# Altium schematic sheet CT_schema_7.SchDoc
size 278 x 170 mm
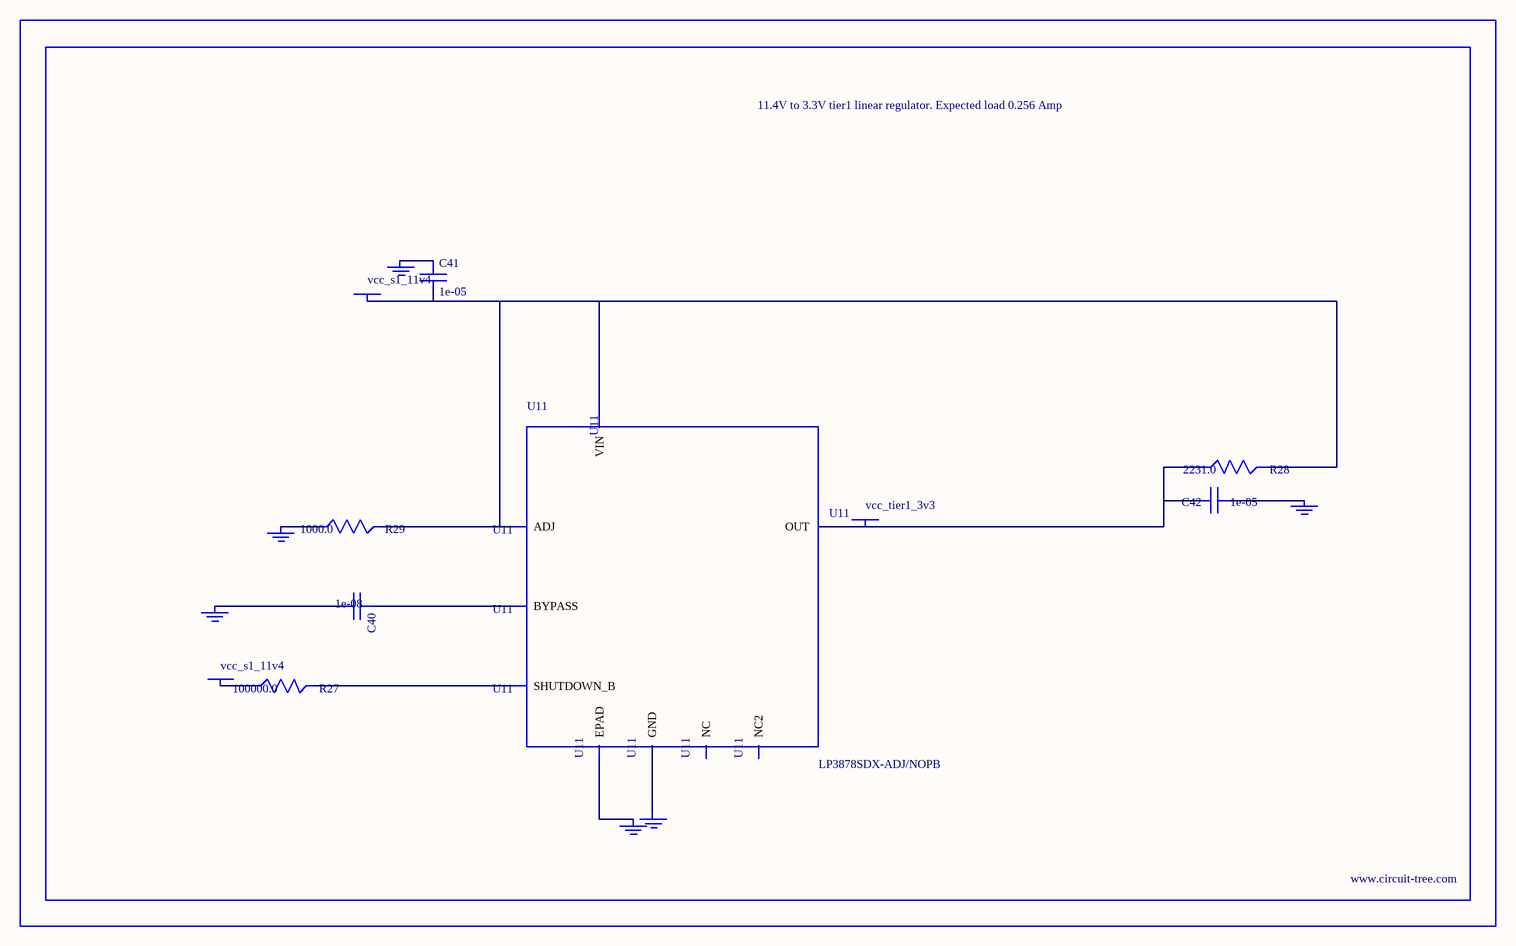
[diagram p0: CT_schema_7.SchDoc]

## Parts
BORDER6  (no value)
C40  1e-08  [C0402]
C41  1e-05  [C1210]
C42  1e-05  [C1210]
GND_INSTANCE_6_0  (no value)
GND_INSTANCE_6_1  (no value)
GND_INSTANCE_6_2  (no value)
GND_INSTANCE_6_3  (no value)
GND_INSTANCE_6_4  (no value)
GND_INSTANCE_6_5  (no value)
POWER_INSTANCE_6_0  vcc_s1_11v4
POWER_INSTANCE_6_1  vcc_s1_11v4
POWER_INSTANCE_6_2  vcc_tier1_3v3
R27  100000.0  [R0603]
R28  2231.0  [R0603]
R29  1000.0  [R0603]
U11  LP3878SDX-ADJ/NOPB  [WSON-8]

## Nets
NetC40_1: C40.1 U11.1(BYPASS)
NetC40_2: C40.2 GND_INSTANCE_6_0.0(GND)
NetC41_1: C41.1 GND_INSTANCE_6_1.0(GND)
NetC41_2: C41.2 POWER_INSTANCE_6_0.0(PWR) R28.2 R29.2 U11.4(VIN) U11.6(ADJ)
NetC42_1: C42.1 GND_INSTANCE_6_2.0(GND)
NetC42_2: C42.2 POWER_INSTANCE_6_2.0(PWR) R28.1 U11.5(OUT)
NetGND_INSTANCE_6_3_0: GND_INSTANCE_6_3.0(GND) R29.1
NetGND_INSTANCE_6_4_0: GND_INSTANCE_6_4.0(GND) U11.PAD(EPAD)
NetGND_INSTANCE_6_5_0: GND_INSTANCE_6_5.0(GND) U11.3(GND)
NetPOWER_INSTANCE_6_1_0: POWER_INSTANCE_6_1.0(PWR) R27.1
NetR27_2: R27.2 U11.8(SHUTDOWN_B)

Not connected (* = marked no-connect by the designer): U11 2(NC) 7(NC2)

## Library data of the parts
BORDER6 = BORDER_PAGE6
C40 = C0402C103K3RAC
C41 = C1210C106K5PACTU
C42 = GRM32DR61E106MA12L
GND_INSTANCE_6_0-GND_INSTANCE_6_5 = GND
POWER_INSTANCE_6_0-POWER_INSTANCE_6_2 = PWR
R27 = RC0603JR-07100KL
R28 = R28
R29 = RC0603JR-071KL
